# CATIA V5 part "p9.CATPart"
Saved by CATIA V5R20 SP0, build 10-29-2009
Part number: p9
Publications: "Line.3", "Point.3", "Plane.2", "Line.4", "Point.4", "Plane.3"
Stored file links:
  D:\Dropbox\IAO_2011\MMS_GR2\IAO_2011_1439_jlicbarski\p9.CATPart
  D:\Dropbox\IAO_2011\MMS_GR2\IAO_2011_1439_jlicbarski\train.CATProduct

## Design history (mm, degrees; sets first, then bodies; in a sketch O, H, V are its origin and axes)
AxisSystem1: origin (0, 0, 0), X (1, 0, 0), Y (0, 1, 0), Z (0, 0, 1)
Set1
  Point1: linked copy from another document
Body1 (main body)
  Line1: type PtDir, RefPoint Point1, Direction edge [XY plane of AxisSystem1 | ZX plane of AxisSystem1], Start 0, End -20
  Point2: type OnCurve, Support Line1, Length 7.5
  Plane1: type Normal, Curve Line1
  Plane2: type Normal, Curve Line1, RefPoint Point2
  Point3: (-12.5, 42, 107.25), in AxisSystem1
  Line2: type PtPt, FirstPoint Point2, SecondPoint Point3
